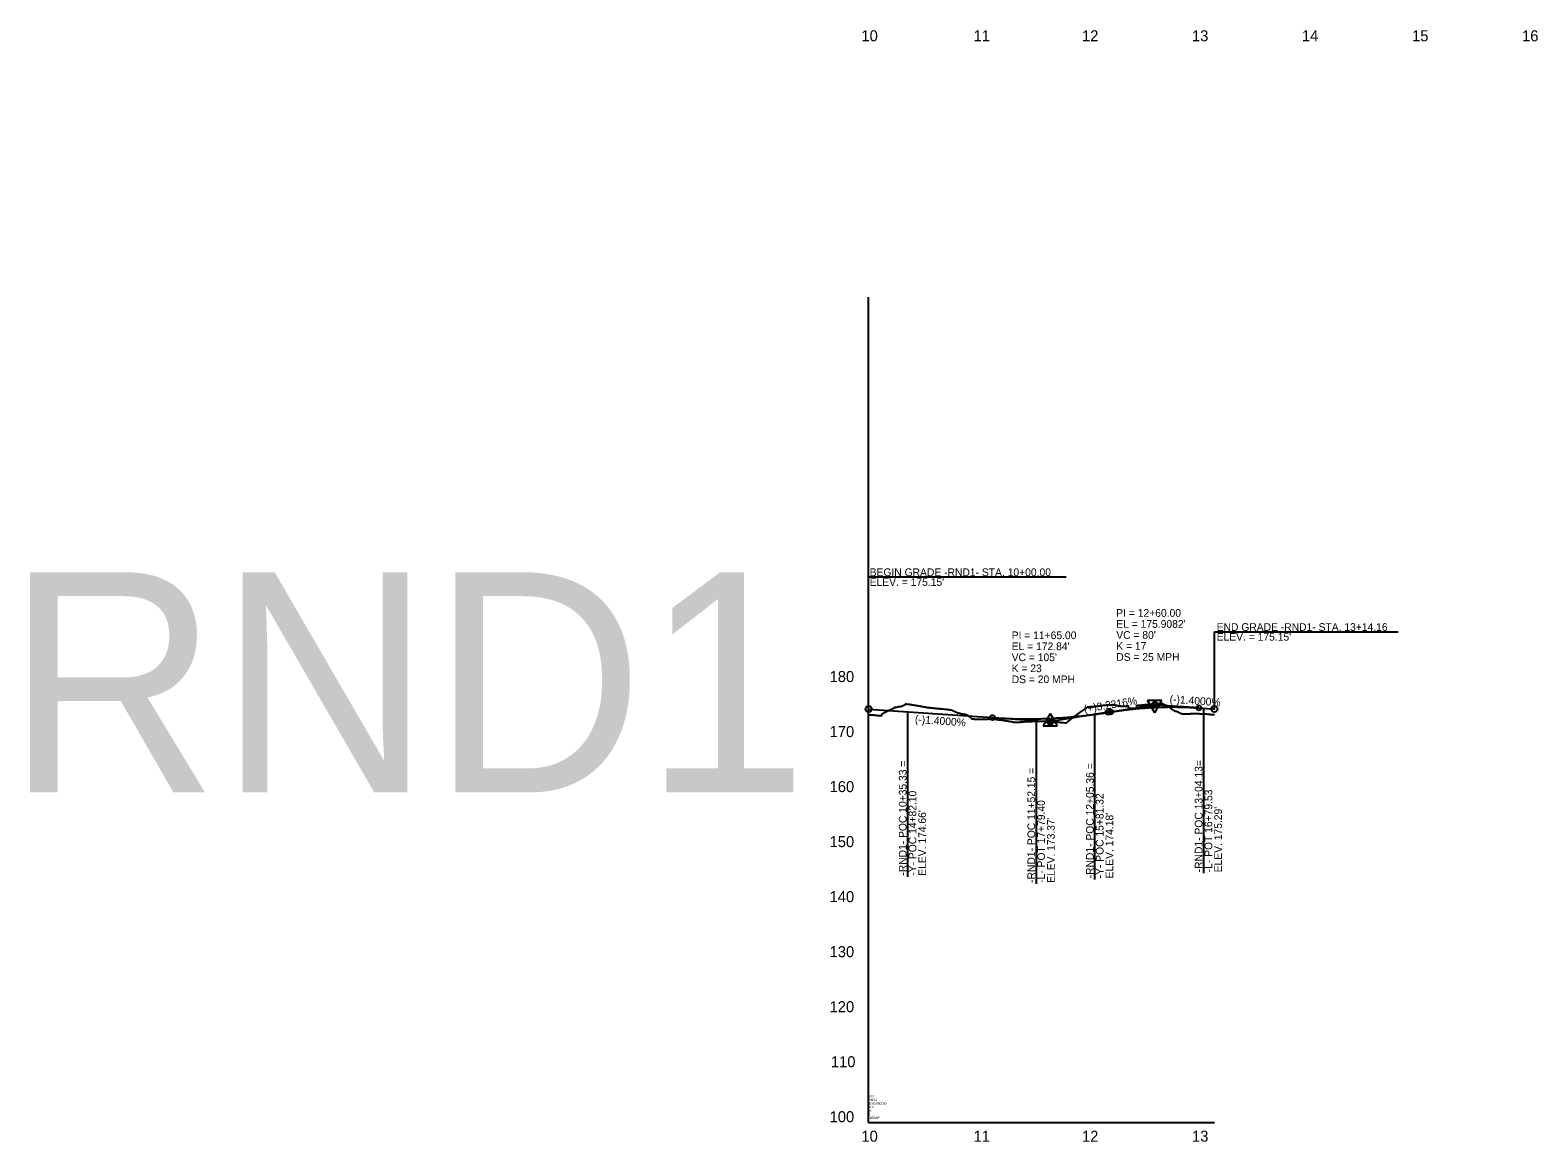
# Model space of a CAD drawing. Extents: x 1778432 to 1784301, y 601022 to 621789.
# Drawn here: x 1779381 to 1780751, y 604022 to 605032 of the extents above; entities that cross this region are included whole.
import ezdxf

# ---------------------------------------------------------------- set-up
doc = ezdxf.new("R2010")
doc.units = 0
for name, color, linetype in [('Exist Profile Cell', 7, 'Continuous'), ('Exist Vertical Profile Ground Line', 7, 'Continuous'), ('Exist Vertical Profile Horizontal Axis Label Major', 7, 'Continuous'), ('Exist Vertical Profile Vertical Axis Label', 7, 'Continuous'), ('Prop PFL Text', 7, 'Continuous'), ('Prop PFL VPI Symbol CELL', 7, 'Continuous'), ('Prop Vertical Profile Curve Label', 7, 'Continuous'), ('Prop Vertical Profile Grade', 7, 'Continuous'), ('Prop Vertical Profile Grade Label', 7, 'Continuous'), ('Prop VPI Label', 7, 'Continuous')]:
    doc.layers.add(name, color=color, linetype=linetype)

msp = doc.modelspace()

# ---------------------------------------------------------------- linework, layer by layer
at = {"layer": 'Exist Profile Cell'}
for q in [(1780143, 604789.2), (1780457.1, 604039.2), (1780143, 604039.2)]:
    msp.add_line((1780143, 604039.2), q, dxfattribs=at)
at = {"layer": 'Exist Vertical Profile Ground Line'}
msp.add_lwpolyline([(1780143, 604409.9), (1780143.6, 604409.8), (1780144.2, 604409.7), (1780144.8, 604409.6), (1780145.5, 604409.5), (1780146.1, 604409.5), (1780146.7, 604409.5), (1780147.4, 604409.5), (1780148, 604409.5), (1780148.6, 604409.4), (1780149.2, 604409.3), (1780149.9, 604409.2), (1780150.9, 604409.1), (1780151.8, 604409), (1780152.4, 604409), (1780153.3, 604408.9), (1780153.6, 604408.9), (1780154.3, 604408.8), (1780154.9, 604409.5), (1780155.5, 604410.1), (1780156.2, 604410.7), (1780157, 604411.5), (1780157.4, 604411.7), (1780158, 604412), (1780158.7, 604412.3), (1780159.3, 604412.6), (1780159.9, 604412.8), (1780160.6, 604413.1), (1780161.2, 604413.5), (1780161.8, 604413.8), (1780162.4, 604414.1), (1780163.2, 604414.5), (1780163.7, 604414.7), (1780164.3, 604415), (1780165, 604415.3), (1780165.6, 604415.6), (1780166.2, 604415.9), (1780166.6, 604416), (1780167, 604416.5), (1780167.5, 604416.5), (1780168.1, 604416.6), (1780168.7, 604416.7), (1780169.3, 604416.8), (1780170, 604416.9), (1780170.6, 604417.1), (1780171.2, 604417.2), (1780171.9, 604417.3), (1780172.6, 604417.4), (1780173.2, 604417.4), (1780173.7, 604417.8), (1780174.4, 604418.1), (1780175, 604418.4), (1780175.6, 604418.8), (1780176.3, 604419.1), (1780177.1, 604419.5), (1780177.5, 604419.5), (1780178.1, 604419.4), (1780178.8, 604419.3), (1780179.4, 604419.3), (1780180.3, 604419.2), (1780180.7, 604419.1), (1780181.3, 604419), (1780181.9, 604418.9), (1780182.5, 604418.8), (1780183.2, 604418.7), (1780183.8, 604418.6), (1780184.4, 604418.5), (1780185.1, 604418.4), (1780185.7, 604418.3), (1780186.3, 604418.2), (1780186.9, 604418.1), (1780187.6, 604418), (1780188.2, 604417.9), (1780189, 604417.7), (1780189.5, 604417.6), (1780190.1, 604417.5), (1780190.7, 604417.4), (1780191.3, 604417.3), (1780192, 604417.2), (1780192.6, 604417.1), (1780193.2, 604417), (1780193.9, 604416.9), (1780194.5, 604416.8), (1780195.1, 604416.7), (1780195.7, 604416.6), (1780196.4, 604416.4), (1780197, 604416.3), (1780197.6, 604416.2), (1780198.3, 604416.2), (1780198.9, 604416.1), (1780199.5, 604416.1), (1780200.1, 604416), (1780200.8, 604415.9), (1780201.4, 604415.9), (1780202, 604415.8), (1780202.7, 604415.8), (1780203.3, 604415.7), (1780203.9, 604415.6), (1780204.5, 604415.6), (1780205.2, 604415.5), (1780205.8, 604415.5), (1780206.4, 604415.4), (1780207, 604415.4), (1780207.7, 604415.3), (1780208.3, 604415.2), (1780208.9, 604415.2), (1780209.6, 604415.1), (1780210.2, 604415), (1780210.8, 604415), (1780211.4, 604414.9), (1780212.1, 604414.9), (1780212.7, 604414.8), (1780213.3, 604414.7), (1780214, 604414.7), (1780214.9, 604414.6), (1780215.2, 604414.5), (1780215.8, 604414.4), (1780216.5, 604414.3), (1780217.1, 604414.2), (1780217.7, 604414.1), (1780218.2, 604414.1), (1780219, 604413.7), (1780219.6, 604413.5), (1780220.2, 604413.2), (1780220.9, 604412.9), (1780221.5, 604412.7), (1780222.1, 604412.4), (1780222.8, 604412.1), (1780223.4, 604411.7), (1780223.8, 604411.4), (1780224.6, 604411.3), (1780225.3, 604411.1), (1780225.9, 604411), (1780226.5, 604410.9), (1780227.2, 604410.8), (1780227.8, 604410.6), (1780228.4, 604410.5), (1780229, 604410.4), (1780229.7, 604410.2), (1780230.3, 604410.1), (1780230.9, 604410), (1780231.6, 604409.8), (1780232.2, 604409.6), (1780232.8, 604409.4), (1780233.2, 604409.2), (1780234.1, 604408.5), (1780234.7, 604408), (1780235.3, 604407.5), (1780236, 604407), (1780236.6, 604406.4), (1780237.1, 604406), (1780237.8, 604405.9), (1780238.5, 604405.9), (1780239.1, 604405.8), (1780239.9, 604405.7), (1780240.3, 604405.7), (1780240.7, 604405.7), (1780241.6, 604405.8), (1780242.2, 604405.8), (1780242.9, 604405.8), (1780243.7, 604405.8), (1780244.1, 604405.7), (1780244.7, 604405.7), (1780246, 604405.6), (1780246.6, 604405.7), (1780247.3, 604405.7), (1780247.9, 604405.7), (1780248.6, 604405.7), (1780249.1, 604405.7), (1780249.8, 604405.7), (1780250.4, 604405.8), (1780251, 604405.8), (1780251.8, 604405.9), (1780252.3, 604405.9), (1780252.9, 604405.8), (1780253.7, 604405.8), (1780254.4, 604405.7), (1780254.8, 604405.7), (1780255.1, 604405.7), (1780255.4, 604405.7), (1780256.1, 604405.7), (1780256.7, 604405.7), (1780257.3, 604405.6), (1780257.9, 604405.6), (1780258.6, 604405.6), (1780259.2, 604405.5), (1780259.8, 604405.4), (1780260.7, 604405.3), (1780261.1, 604405.2), (1780261.7, 604405.2), (1780262.6, 604405.1), (1780263, 604405.1), (1780263.6, 604405), (1780263.9, 604404.9), (1780264.2, 604404.9), (1780264.9, 604404.8), (1780265.5, 604404.7), (1780266.1, 604404.6), (1780266.8, 604404.5), (1780267.4, 604404.4), (1780268, 604404.3), (1780268.7, 604404.2), (1780269.3, 604404.1), (1780269.9, 604404), (1780270.5, 604403.9), (1780271.1, 604403.8), (1780271.9, 604403.7), (1780272.6, 604403.6), (1780273, 604403.5), (1780273.7, 604403.4), (1780274.3, 604403.2), (1780274.9, 604403.1), (1780275.5, 604403), (1780276.2, 604403), (1780276.8, 604403), (1780277.4, 604403), (1780278.3, 604403), (1780278.7, 604403), (1780279.3, 604403.1), (1780279.9, 604403.1), (1780280.7, 604403.1), (1780281.2, 604403.2), (1780282.1, 604403.3), (1780282.4, 604403.3), (1780283.3, 604403.4), (1780283.7, 604403.4), (1780284.3, 604403.4), (1780285.2, 604403.5), (1780285.9, 604403.5), (1780286.2, 604403.5), (1780286.8, 604403.5), (1780287.5, 604403.6), (1780288.4, 604403.7), (1780288.8, 604403.7), (1780289.4, 604403.7), (1780290, 604403.7), (1780290.9, 604403.7), (1780291.2, 604403.7), (1780291.9, 604403.8), (1780292.5, 604403.8), (1780293.4, 604403.9), (1780293.8, 604403.9), (1780294.4, 604403.9), (1780295, 604403.9), (1780295.9, 604403.9), (1780296.3, 604403.9), (1780296.9, 604403.8), (1780297.5, 604403.8), (1780298.4, 604403.8), (1780298.8, 604403.8), (1780299.4, 604403.8), (1780300, 604403.9), (1780300.9, 604403.9), (1780301.3, 604403.9), (1780302.2, 604403.8), (1780302.6, 604403.8), (1780303.8, 604403.8), (1780304.4, 604403.8), (1780305.1, 604403.8), (1780306, 604403.7), (1780306.3, 604403.7), (1780307, 604403.6), (1780307.6, 604403.6), (1780308.2, 604403.5), (1780308.8, 604403.4), (1780309.5, 604403.4), (1780310.4, 604403.4), (1780310.7, 604403.3), (1780311.3, 604403.3), (1780312, 604403.3), (1780312.7, 604403.3), (1780313.2, 604403.2), (1780313.9, 604403.2), (1780314.5, 604403.2), (1780315.4, 604403.1), (1780315.7, 604403.1), (1780316.5, 604403), (1780317, 604402.9), (1780317.6, 604402.8), (1780318.3, 604402.7), (1780319.5, 604402.5), (1780320.1, 604402.5), (1780320.7, 604402.5), (1780321.4, 604402.3), (1780322.1, 604402.2), (1780322.7, 604402.6), (1780323.3, 604403.1), (1780323.9, 604403.6), (1780324.5, 604404.1), (1780325.2, 604404.5), (1780325.8, 604405), (1780326.4, 604405.5), (1780327.1, 604406), (1780327.7, 604406.5), (1780328.3, 604407), (1780328.9, 604407.5), (1780329.6, 604408), (1780330.2, 604408.5), (1780330.8, 604408.9), (1780331.5, 604409.4), (1780332.1, 604409.8), (1780332.7, 604410.3), (1780333.3, 604410.7), (1780334, 604411.2), (1780334.6, 604411.6), (1780335.2, 604412.1), (1780335.9, 604412.5), (1780336.5, 604413), (1780337.1, 604413.4), (1780337.7, 604413.9), (1780338.4, 604414.3), (1780339, 604414.8), (1780339.6, 604415.2), (1780340.3, 604415.6), (1780340.9, 604416.1), (1780341.5, 604416.5), (1780341.8, 604416.8), (1780342.8, 604416.8), (1780343.4, 604416.9), (1780344, 604416.9), (1780344.7, 604417), (1780345.3, 604417), (1780345.9, 604417.1), (1780346.5, 604417.1), (1780347.2, 604417.2), (1780347.8, 604417.2), (1780348.4, 604417.3), (1780349, 604417.4), (1780349.7, 604417.5), (1780350.3, 604417.5), (1780350.9, 604417.6), (1780351.6, 604417.7), (1780352.2, 604417.8), (1780352.8, 604417.9), (1780353.4, 604418), (1780354.1, 604418), (1780354.7, 604418.1), (1780355.3, 604418.2), (1780356, 604418.3), (1780356.8, 604418.5), (1780357.2, 604418.5), (1780357.8, 604418.5), (1780358.5, 604418.5), (1780359.1, 604418.6), (1780359.7, 604418.6), (1780360.4, 604418.7), (1780361, 604418.7), (1780361.6, 604418.7), (1780362.2, 604418.8), (1780362.9, 604418.8), (1780363.5, 604418.8), (1780364.1, 604418.8), (1780365, 604418.9), (1780365.4, 604418.8), (1780366, 604418.7), (1780366.6, 604418.6), (1780367.3, 604418.5), (1780367.9, 604418.3), (1780368.5, 604418.2), (1780369.2, 604418.1), (1780369.8, 604418), (1780370.4, 604417.9), (1780371, 604417.8), (1780371.7, 604417.7), (1780372.3, 604417.6), (1780373.2, 604417.4), (1780373.8, 604417.4), (1780374.2, 604417.4), (1780374.8, 604417.5), (1780375.4, 604417.5), (1780376.1, 604417.5), (1780376.7, 604417.6), (1780377.3, 604417.6), (1780378, 604417.6), (1780378.6, 604417.7), (1780378.9, 604417.7), (1780379, 604415.6), (1780379.8, 604415.6), (1780380.5, 604415.6), (1780381.1, 604415.6), (1780381.7, 604415.6), (1780382.3, 604415.6), (1780383, 604415.7), (1780383.6, 604415.7), (1780384.2, 604415.7), (1780384.9, 604415.8), (1780385.5, 604415.8), (1780386.3, 604415.8), (1780386.7, 604418.2), (1780387.4, 604418.3), (1780388, 604418.3), (1780388.6, 604418.4), (1780389.3, 604418.4), (1780389.9, 604418.5), (1780390.5, 604418.5), (1780391.4, 604418.6), (1780391.9, 604418.6), (1780392.4, 604418.7), (1780393, 604418.8), (1780393.7, 604418.8), (1780394.3, 604418.9), (1780394.9, 604419), (1780395.5, 604419), (1780396.2, 604419), (1780396.8, 604419), (1780397.5, 604419), (1780398.1, 604419.1), (1780398.7, 604419.2), (1780399.3, 604419.3), (1780399.9, 604419.4), (1780400.6, 604419.5), (1780401.2, 604419.6), (1780401.8, 604419.7), (1780402.5, 604419.8), (1780403.1, 604419.9), (1780403.7, 604419.9), (1780404.3, 604419.9), (1780405, 604419.9), (1780405.6, 604419.9), (1780406.2, 604419.9), (1780406.9, 604419.9), (1780407.5, 604419.9), (1780408.1, 604419.9), (1780408.7, 604419.9), (1780409.4, 604419.9), (1780410.2, 604419.9), (1780410.6, 604419.7), (1780411.3, 604419.3), (1780411.9, 604419), (1780412.5, 604418.7), (1780413.1, 604418.3), (1780413.8, 604418), (1780414.4, 604417.6), (1780415, 604417.2), (1780415.7, 604416.9), (1780416.4, 604416.5), (1780416.9, 604416.1), (1780417.5, 604415.7), (1780418.2, 604415.2), (1780418.8, 604414.8), (1780419.4, 604414.3), (1780420.2, 604413.8), (1780420.7, 604413.6), (1780421.3, 604413.3), (1780421.9, 604413), (1780422.6, 604412.8), (1780423.2, 604412.5), (1780423.8, 604412.2), (1780424.4, 604411.9), (1780425.1, 604411.6), (1780425.7, 604411.3), (1780426.3, 604411), (1780427, 604410.7), (1780427.7, 604410.3), (1780428.4, 604410.4), (1780428.8, 604410.4), (1780429.4, 604410.5), (1780430.1, 604410.5), (1780430.7, 604410.5), (1780431.6, 604410.5), (1780432, 604410.5), (1780432.6, 604410.5), (1780433.2, 604410.6), (1780433.9, 604410.6), (1780434.5, 604410.6), (1780435.3, 604410.6), (1780435.8, 604410.7), (1780436.4, 604410.7), (1780437, 604410.7), (1780437.6, 604410.7), (1780438.3, 604410.7), (1780438.9, 604410.7), (1780439.6, 604410.7), (1780440.2, 604410.7), (1780441.2, 604410.8), (1780442.1, 604410.7), (1780442.7, 604410.7), (1780443.3, 604410.7), (1780443.9, 604410.6), (1780444.6, 604410.6), (1780445.2, 604410.6), (1780445.8, 604410.6), (1780446.4, 604410.6), (1780447.2, 604410.6), (1780447.7, 604410.6), (1780448.3, 604410.5), (1780449.1, 604410.4), (1780449.7, 604410.4), (1780450.2, 604410.4), (1780451.1, 604410.3), (1780451.5, 604410.3), (1780452.2, 604410.3), (1780452.7, 604410.2), (1780453.4, 604410.1), (1780454, 604410), (1780454.7, 604409.9), (1780455.2, 604409.9), (1780455.9, 604409.9), (1780456.5, 604409.9), (1780457.1, 604409.9)], dxfattribs=at)
at = {"layer": 'Prop PFL VPI Symbol CELL'}
for p, q in [((1780403, 604411.4), (1780396.5, 604422.6)), ((1780409.5, 604422.6), (1780396.5, 604422.6)), ((1780403, 604411.4), (1780409.5, 604422.6)), ((1780307.9, 604410.7), (1780301.5, 604399.5)), ((1780301.5, 604399.5), (1780314.4, 604399.5)), ((1780307.9, 604410.7), (1780314.4, 604399.5))]:
    msp.add_line(p, q, dxfattribs=at)
for centre, radius in [((1780403, 604418.9), 1.75), ((1780403, 604418.9), 1.2), ((1780307.9, 604403.3), 1.75), ((1780307.9, 604403.3), 1.2)]:
    msp.add_circle(centre, radius, dxfattribs=at)
at = {"layer": 'Prop Vertical Profile Curve Label'}
for centre in [(1780360.5, 604411.9), (1780363, 604412.3), (1780443, 604415.9), (1780255.5, 604407.1)]:
    msp.add_circle(centre, 2.25, dxfattribs=at)
at = {"layer": 'Prop Vertical Profile Grade'}
for p, q in [((1780143, 604414.9), (1780255.5, 604407.1)), ((1780443, 604415.9), (1780457.1, 604414.9)), ((1780360.5, 604411.9), (1780363, 604412.3))]:
    msp.add_line(p, q, dxfattribs=at)
for points in [[(1780363, 604412.3), (1780364.6, 604412.5), (1780366.2, 604412.8), (1780367.8, 604413), (1780369.4, 604413.2), (1780371, 604413.5), (1780372.6, 604413.7), (1780374.2, 604413.9), (1780375.8, 604414.1), (1780377.4, 604414.3), (1780379, 604414.5), (1780380.6, 604414.7), (1780382.2, 604414.8), (1780383.8, 604415), (1780385.4, 604415.2), (1780387, 604415.3), (1780388.6, 604415.5), (1780390.2, 604415.6), (1780391.8, 604415.7), (1780393.4, 604415.8), (1780395, 604416), (1780396.6, 604416.1), (1780398.2, 604416.2), (1780399.8, 604416.3), (1780401.4, 604416.3), (1780403, 604416.4), (1780404.6, 604416.5), (1780406.2, 604416.5), (1780407.8, 604416.6), (1780409.4, 604416.7), (1780411, 604416.7), (1780412.6, 604416.7), (1780414.2, 604416.7), (1780415.8, 604416.8), (1780417.4, 604416.8), (1780419, 604416.8), (1780420.6, 604416.8), (1780422.2, 604416.8), (1780423.8, 604416.7), (1780425.4, 604416.7), (1780427, 604416.7), (1780428.6, 604416.6), (1780430.2, 604416.6), (1780431.8, 604416.5), (1780433.4, 604416.5), (1780435, 604416.4), (1780436.6, 604416.3), (1780438.2, 604416.2), (1780439.8, 604416.1), (1780441.4, 604416), (1780443, 604415.9)], [(1780255.5, 604407.1), (1780257.6, 604406.9), (1780259.7, 604406.8), (1780261.8, 604406.7), (1780263.9, 604406.6), (1780266, 604406.5), (1780268.1, 604406.4), (1780270.2, 604406.3), (1780272.3, 604406.2), (1780274.4, 604406.1), (1780276.5, 604406.1), (1780278.6, 604406), (1780280.7, 604406), (1780282.8, 604406), (1780284.9, 604406), (1780287, 604406), (1780289.1, 604406), (1780291.2, 604406), (1780293.3, 604406), (1780295.4, 604406), (1780297.5, 604406.1), (1780299.6, 604406.1), (1780301.7, 604406.2), (1780303.8, 604406.3), (1780305.9, 604406.3), (1780308, 604406.4), (1780310.1, 604406.5), (1780312.2, 604406.6), (1780314.3, 604406.8), (1780316.4, 604406.9), (1780318.5, 604407), (1780320.6, 604407.2), (1780322.7, 604407.3), (1780324.8, 604407.5), (1780326.9, 604407.7), (1780329, 604407.9), (1780331.1, 604408.1), (1780333.2, 604408.3), (1780335.3, 604408.5), (1780337.4, 604408.7), (1780339.5, 604409), (1780341.6, 604409.2), (1780343.7, 604409.5), (1780345.8, 604409.7), (1780347.9, 604410), (1780350, 604410.3), (1780352.1, 604410.6), (1780354.2, 604410.9), (1780356.3, 604411.2), (1780358.4, 604411.5), (1780360.5, 604411.9)]]:
    msp.add_spline(points, degree=3, dxfattribs=at)
at = {"layer": 'Prop VPI Label'}
for p, q in [((1780143, 604534.9), (1780322.6, 604534.9)), ((1780143, 604414.9), (1780143, 604534.9)), ((1780457.1, 604414.9), (1780457.1, 604484.9)), ((1780457.1, 604484.9), (1780624.1, 604484.9)), ((1780178.3, 604412.5), (1780178.3, 604262.5)), ((1780363, 604412.3), (1780400.2, 604418.3)), ((1780443, 604415.9), (1780405.7, 604418.5)), ((1780447.1, 604415.6), (1780447.1, 604265.6)), ((1780255.5, 604407.1), (1780305.2, 604403.6)), ((1780295.1, 604406), (1780295.1, 604256)), ((1780360.5, 604411.9), (1780310.7, 604403.8)), ((1780348.3, 604410.1), (1780348.3, 604260.1))]:
    msp.add_line(p, q, dxfattribs=at)
for centre in [(1780143, 604414.9), (1780403, 604418.7), (1780457.1, 604414.9), (1780308, 604403.4)]:
    msp.add_circle(centre, 2.75, dxfattribs=at)

# ---------------------------------------------------------------- texts
at = {"layer": 'Exist Profile Cell'}
for s, p in [('RDY', (1780143, 604061.9)), ('RND1', (1780143, 604058.7)), ('1000.000000', (1780143, 604055.4)), ('2', (1780143, 604045.7)), ('100', (1780143, 604052.2)), ('10', (1780143, 604048.9)), ('NOGAP', (1780143, 604042.4))]:
    msp.add_text(s, height=2, dxfattribs=at).set_placement(p)
at = {"layer": 'Exist Vertical Profile Horizontal Axis Label Major'}
for s, p in [('10', (1780136.5, 605021.7)), ('11', (1780238.4, 605021.7)), ('12', (1780336.9, 605021.7)), ('13', (1780436.8, 605021.7)), ('14', (1780536.6, 605021.7)), ('15', (1780636.7, 605021.7)), ('16', (1780736.6, 605021.7)), ('10', (1780136.5, 604021.7)), ('10', (1780136.5, 604021.7)), ('11', (1780238.4, 604021.7)), ('11', (1780238.4, 604021.7)), ('12', (1780336.9, 604021.7)), ('12', (1780336.9, 604021.7)), ('13', (1780436.8, 604021.7)), ('13', (1780436.8, 604021.7))]:
    msp.add_text(s, height=10, dxfattribs=at).set_placement(p)
at = {"layer": 'Exist Vertical Profile Vertical Axis Label'}
for s, p in [('180', (1780107.6, 604439.4)), ('180', (1780107.6, 604439.4)), ('170', (1780107.6, 604389.4)), ('170', (1780107.6, 604389.4)), ('160', (1780107.6, 604339.4)), ('160', (1780107.6, 604339.4)), ('150', (1780107.6, 604289.4)), ('150', (1780107.6, 604289.4)), ('140', (1780107.6, 604239.4)), ('140', (1780107.6, 604239.4)), ('130', (1780107.6, 604189.4)), ('130', (1780107.6, 604189.4)), ('120', (1780107.6, 604139.4)), ('120', (1780107.6, 604139.4)), ('110', (1780108.8, 604089.4)), ('110', (1780108.8, 604089.4)), ('100', (1780107.6, 604039.4)), ('100', (1780107.6, 604039.4))]:
    msp.add_text(s, height=10, dxfattribs=at).set_placement(p)
at = {"layer": 'Prop PFL Text'}
msp.add_text('RND1', height=200, dxfattribs=at).set_placement((1779359.5, 604339.2))
at = {"layer": 'Prop Vertical Profile Curve Label'}
for s, p in [("VC = 80'", (1780368, 604478.7)), ('K = 17', (1780368, 604468.7)), ("VC = 105'", (1780273, 604458.4)), ('K = 23', (1780273, 604448.4)), ('DS = 25 MPH', (1780368, 604458.7)), ('DS = 20 MPH', (1780273, 604438.4))]:
    msp.add_text(s, height=7, dxfattribs=at).set_placement(p)
at = {"layer": 'Prop Vertical Profile Grade Label'}
for s, rotation, p in [('(-)1.4000%', 355.9958, (1780416.3, 604420.6)), ('(+)3.2316%', 9.1733, (1780339.2, 604411.5)), ('(-)1.4000%', 355.9958, (1780184.9, 604402.3))]:
    msp.add_text(s, height=7, rotation=rotation, dxfattribs=at).set_placement(p)
at = {"layer": 'Prop VPI Label'}
for s, p in [('BEGIN GRADE -RND1- STA. 10+00.00', (1780144, 604535.7)), ("ELEV. = 175.15'", (1780144, 604526.8)), ('PI = 12+60.00', (1780368, 604498.7)), ("EL = 175.9082'", (1780368, 604488.7)), ('PI = 11+65.00', (1780273, 604478.4)), ('END GRADE -RND1- STA. 13+14.16', (1780459.2, 604485.9)), ("ELEV. = 175.15'", (1780459.2, 604477)), ("EL = 172.84'", (1780273, 604468.4))]:
    msp.add_text(s, height=7, dxfattribs=at).set_placement(p)
for s, p in [('-RND1- POC 10+35.33 =', (1780177.5, 604263.4)), ('-RND1- POC 11+52.15 =', (1780294.3, 604256.9)), ('-RND1- POC 12+05.36 =', (1780347.5, 604261)), ('-RND1- POC 13+04.13=', (1780446.3, 604266.5)), ('-Y- POC 14+82.10', (1780186.4, 604263.4)), ('-L- POT 17+79.40', (1780303.2, 604256.9)), ('-Y- POC 15+81.32', (1780356.4, 604261)), ('-L- POT 16+79.53', (1780455.2, 604266.5)), ("ELEV. 174.66'", (1780195.2, 604263.4)), ("ELEV. 174.18'", (1780365.3, 604261)), ("ELEV. 175.29'", (1780464, 604266.5)), ("ELEV. 173.37'", (1780312.1, 604256.9))]:
    msp.add_text(s, height=7, rotation=90, dxfattribs=at).set_placement(p)

doc.saveas('drawing.dxf')
